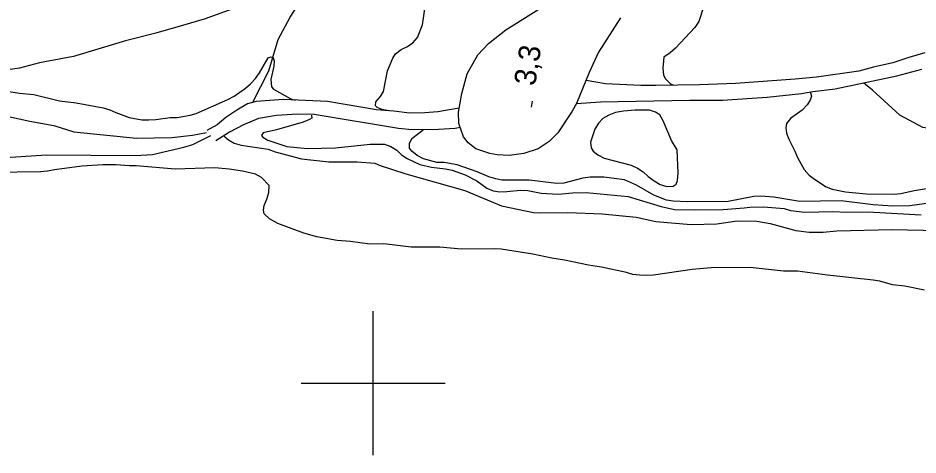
# Model space of a CAD drawing. Extents: x 282461 to 284471, y 5554090 to 5557646.
# Drawn here: x 283150.7 to 283275.7, y 5554590 to 5554650.7 of the extents above; entities that cross this region are included whole.
import ezdxf

# ---------------------------------------------------------------- set-up
doc = ezdxf.new("R2010")
doc.units = 0
for name, color, linetype in [('Niveau 19', 7, 'Continuous'), ('Niveau 2', 7, 'Continuous'), ('Niveau 21', 7, 'Continuous'), ('Niveau 22', 7, 'Continuous'), ('Niveau 3', 7, 'Continuous'), ('Niveau 4', 7, 'Continuous'), ('Niveau 61', 7, 'Continuous')]:
    doc.layers.add(name, color=color, linetype=linetype)

msp = doc.modelspace()

# ---------------------------------------------------------------- linework, layer by layer
at = {"layer": 'Niveau 19'}
for points in [[(283276.62, 5554645.88), (283274.39, 5554645.24), (283272.2, 5554644.48), (283269.52, 5554643.91), (283267.45, 5554643.35), (283261.6, 5554642.52), (283258.63, 5554642.23), (283250.32, 5554641.63), (283245.34, 5554641.44), (283239.25, 5554641.34), (283237.17, 5554641.33), (283232.28, 5554641.59), (283229.59, 5554642.06)], [(283228.24, 5554638.85), (283231.59, 5554639.06), (283243.92, 5554639.3), (283248.51, 5554639.3), (283254.73, 5554639.75), (283259.48, 5554640.23), (283261.06, 5554640.5), (283264.17, 5554640.87), (283272.76, 5554642.67), (283276.22, 5554643.61)], [(283211.95, 5554638.22), (283208.99, 5554637.71), (283207.19, 5554637.55), (283205.05, 5554637.5), (283202.9, 5554637.8), (283200.46, 5554637.99), (283193.65, 5554639.13), (283187.55, 5554639.39), (283183.78, 5554639.14), (283182.56, 5554638.82), (283181.06, 5554637.92), (283179.57, 5554636.89), (283178.36, 5554635.87), (283176.92, 5554635.08)], [(283212.09, 5554635.52), (283211.4, 5554635.38), (283209.08, 5554635.22), (283205.43, 5554635.18), (283203.52, 5554635.37), (283191.82, 5554637.31), (283189.55, 5554637.38), (283186.59, 5554637.2), (283184.1, 5554636.75), (283182.02, 5554635.89), (283180.06, 5554634.86), (283178.16, 5554633.64)]]:
    msp.add_lwpolyline(points, dxfattribs=at)
at = {"layer": 'Niveau 2'}
for points in [[(283202.19, 5554637.81), (283201.27, 5554638.03), (283200.57, 5554638.31), (283200.33, 5554638.54), (283200.38, 5554639.06), (283201.01, 5554639.82), (283201.46, 5554640.53), (283201.99, 5554643.38), (283202.72, 5554645.13), (283203.12, 5554645.77), (283203.92, 5554646.36), (283204.78, 5554646.78), (283205.53, 5554647.26), (283206.15, 5554648.02), (283206.88, 5554649.77), (283207.3, 5554652.62)], [(283245.85, 5554652.09), (283245.24, 5554650.23), (283244.68, 5554649.41), (283242, 5554646.53), (283241.25, 5554645.88), (283240.39, 5554645.29), (283240.24, 5554643.78), (283240.32, 5554642.79), (283240.61, 5554642.28), (283241.32, 5554641.59), (283241.76, 5554641.38)], [(283148.18, 5554640.7), (283150.91, 5554640.28), (283152.89, 5554640.08), (283156.44, 5554639.21), (283158.77, 5554638.95), (283162.49, 5554638.26), (283163.43, 5554637.98), (283164.25, 5554637.59), (283166.11, 5554636.92), (283167.86, 5554636.6), (283168.85, 5554636.56), (283169.83, 5554636.63), (283171.8, 5554636.89), (283172.79, 5554636.91), (283174.58, 5554637.23), (283175.45, 5554637.47), (283179.83, 5554639.4), (283180.69, 5554639.87), (283182.3, 5554641), (283182.99, 5554641.59), (283183.67, 5554642.3), (283184.24, 5554643.12), (283185.42, 5554645.17), (283185.83, 5554645.35), (283186.12, 5554645.18), (283186.24, 5554644.78), (283186.2, 5554644.02), (283185.82, 5554642.16), (283185.9, 5554641.18), (283186.19, 5554640.83), (283188.59, 5554639.48), (283189.16, 5554639.3)], [(283260.76, 5554640.39), (283260.89, 5554639.87), (283260.72, 5554639.29), (283260.27, 5554638.64), (283259.58, 5554637.94), (283257.98, 5554636.75), (283257.41, 5554636.05), (283257.3, 5554635.47), (283257.43, 5554634.72), (283257.73, 5554633.91), (283258.57, 5554632.24), (283258.94, 5554631.32), (283259.89, 5554629.66), (283260.54, 5554628.91), (283261.3, 5554628.35), (283262.94, 5554627.27), (283263.76, 5554626.94), (283265.62, 5554626.56), (283266.55, 5554626.46), (283268.52, 5554626.31), (283272.35, 5554626.26), (283273.28, 5554626.33), (283275.13, 5554626.77), (283276.92, 5554627.03)], [(283242.22, 5554632.39), (283241.45, 5554633.71), (283240.3, 5554636.42), (283239.82, 5554637.28), (283239.24, 5554637.62), (283238.37, 5554637.9), (283236.39, 5554637.92), (283234.77, 5554637.78), (283233.68, 5554637.59), (283232.75, 5554637.23), (283231.89, 5554636.75), (283231.32, 5554636.11), (283230.81, 5554635.29), (283230.2, 5554633.48), (283230.28, 5554632.67), (283230.57, 5554632.21), (283231.22, 5554631.7), (283232.1, 5554631.25), (283235.82, 5554630.27), (283236.7, 5554629.87), (283237.52, 5554629.37), (283238.22, 5554628.68), (283239.04, 5554628.11), (283239.86, 5554627.61), (283240.8, 5554627.33), (283241.66, 5554627.34), (283242.07, 5554627.64), (283242.29, 5554628.17), (283242.39, 5554629.15), (283242.22, 5554632.39)], [(283147.84, 5554637.35), (283152.33, 5554636.37), (283155.65, 5554635.79), (283158.45, 5554634.9), (283167.12, 5554634.05), (283172.06, 5554634.13), (283174.9, 5554634.46), (283176.85, 5554634.81)], [(283191.44, 5554637.22), (283191.48, 5554636.79), (283191.19, 5554636.62), (283190.27, 5554636.25), (283186.57, 5554635.21), (283184.72, 5554634.77), (283184.49, 5554634.42), (283184.67, 5554634.19)], [(283279.21, 5554625.27), (283274.52, 5554624.62), (283272.15, 5554624.58), (283269.47, 5554624.77), (283265, 5554625.34), (283259.25, 5554625.25), (283255.65, 5554625.83), (283253.85, 5554625.98), (283252.86, 5554625.91), (283249.33, 5554625.21), (283243.65, 5554625.18), (283241.67, 5554625.27), (283240.74, 5554625.43), (283238.99, 5554626.1), (283236.59, 5554627.51), (283234.9, 5554628.23), (283232.05, 5554628.6), (283230.13, 5554628.62), (283229.15, 5554628.49), (283226.49, 5554627.76), (283225.51, 5554627.74), (283221.67, 5554628.2), (283217.9, 5554628.2), (283217.03, 5554628.36), (283216.09, 5554628.64), (283214.46, 5554629.37), (283211.66, 5554630.31), (283209.86, 5554630.63), (283208.87, 5554630.67), (283207, 5554631.16), (283206.13, 5554631.61), (283205.36, 5554632.24), (283205.07, 5554632.64), (283205.06, 5554633.28), (283205.39, 5554633.98), (283206.97, 5554635.18)], [(283179.3, 5554634.32), (283179.9, 5554633.79), (283180.72, 5554633.34), (283181.66, 5554633.06), (283185.44, 5554632.48), (283186.38, 5554632.15), (283190.05, 5554631.16), (283193.84, 5554630.75), (283197.79, 5554630.76), (283200.23, 5554630.56), (283200.99, 5554630.23), (283204.55, 5554629.06), (283212.72, 5554626.75), (283217.81, 5554624.62), (283222.3, 5554623.71), (283223.29, 5554623.66), (283227.06, 5554623.72), (283231.83, 5554623.51), (283236.54, 5554623.06), (283239.29, 5554622.46), (283244.17, 5554622.01), (283247.72, 5554622.13), (283250.56, 5554622.52), (283253.29, 5554622.51), (283255.15, 5554622.19), (283258.71, 5554621.2), (283260.58, 5554620.99), (283262.5, 5554620.96), (283264.41, 5554621.17), (283272.02, 5554621.35), (283278.59, 5554621.22)], [(283184.67, 5554634.19), (283185.38, 5554633.74), (283188, 5554632.85), (283190.91, 5554632.61), (283194.8, 5554632.67), (283199.61, 5554633.21), (283201.58, 5554633.18), (283202.46, 5554632.85), (283203.28, 5554632.34), (283203.93, 5554631.71), (283204.75, 5554631.2), (283206.5, 5554630.36), (283208.13, 5554629.98), (283210.05, 5554629.77), (283210.98, 5554629.56), (283212.79, 5554628.95), (283214.43, 5554628.1), (283215.78, 5554627.08), (283216.66, 5554626.69), (283217.59, 5554626.58), (283218.58, 5554626.6), (283220.49, 5554626.8), (283221.48, 5554626.76), (283223.34, 5554626.38), (283225.72, 5554626.25), (283227.69, 5554626.45), (283229.61, 5554626.48), (283235.42, 5554625.93), (283240.03, 5554624.55), (283241.84, 5554624.12), (283244.69, 5554624.05), (283248.63, 5554624.11), (283251.53, 5554624.33), (283252.34, 5554624.46), (283254.2, 5554624.49), (283257.11, 5554624.24), (283257.98, 5554623.96), (283259.96, 5554623.76), (283263.85, 5554623.82), (283265.77, 5554623.74), (283268.73, 5554623.78), (283276.11, 5554623.38)]]:
    msp.add_lwpolyline(points, dxfattribs=at)
at = {"layer": 'Niveau 21'}
msp.add_lwpolyline([(283234.34, 5554650.74), (283231.31, 5554645.98), (283230.02, 5554643.15), (283228.24, 5554638.85), (283227.67, 5554637.78), (283225.66, 5554634.76), (283224.43, 5554633.58), (283222.91, 5554632.54), (283220.95, 5554631.88), (283218.9, 5554631.61), (283217.21, 5554631.7), (283216.22, 5554631.89), (283214.27, 5554632.55), (283213.21, 5554633.4), (283212.56, 5554634.2), (283211.9, 5554636.07), (283211.84, 5554637.63), (283212.32, 5554640.25), (283213.06, 5554642.99), (283214.53, 5554645.61), (283216.01, 5554647.19), (283218.45, 5554649.09), (283225.39, 5554653.49)], dxfattribs=at)
at = {"layer": 'Niveau 22'}
for points in [[(283183.28, 5554639.01), (283185.51, 5554643.37), (283186.83, 5554647.74), (283188.47, 5554650.84), (283191.7, 5554655.9), (283194.32, 5554658.84), (283199.12, 5554663.61), (283201.4, 5554666.26), (283203.17, 5554668.15), (283204.71, 5554669.51), (283207.19, 5554670.94), (283218.89, 5554675.85)], [(283189.97, 5554656.34), (283187.82, 5554654.98), (283184.48, 5554653.47), (283176.52, 5554650.57), (283173.52, 5554649.67), (283169.83, 5554648.62), (283165.61, 5554647.57), (283158.39, 5554645.37), (283153.65, 5554644.5), (283150.88, 5554643.76), (283147.93, 5554643.36), (283143.4, 5554643.04), (283140.95, 5554642.24)], [(283291.45, 5554620.48), (283291.23, 5554622.56), (283289.87, 5554627.4), (283288.81, 5554630.8), (283287.03, 5554633.91), (283286.21, 5554634.65), (283285.57, 5554634.99), (283283.61, 5554635.28), (283281.24, 5554635.07), (283279.44, 5554635.04), (283276.36, 5554635.51), (283273.14, 5554637.21), (283269.36, 5554640.71), (283268.17, 5554641.68)], [(283147.47, 5554631.23), (283154.66, 5554631.73), (283166.97, 5554631.62), (283169.35, 5554631.78), (283173.7, 5554632.79), (283174.97, 5554633.15), (283177.45, 5554634.38)]]:
    msp.add_lwpolyline(points, dxfattribs=at)
at = {"layer": 'Niveau 3'}
msp.add_line((283222.02, 5554638.36), (283222.14, 5554639.15), dxfattribs=at)
at = {"layer": 'Niveau 4'}
msp.add_lwpolyline([(283276.56, 5554612.91), (283273.87, 5554613.45), (283272.12, 5554613.66), (283270.37, 5554614.15), (283269.44, 5554614.31), (283263.09, 5554614.97), (283258.95, 5554615.54), (283256.98, 5554615.57), (283252.37, 5554616.08), (283246.97, 5554616), (283244.3, 5554615.78), (283238.96, 5554615), (283237.97, 5554614.93), (283236.99, 5554614.97), (283236.05, 5554615.07), (283235.18, 5554615.35), (283231.73, 5554616.11), (283229.93, 5554616.37), (283226.6, 5554617.07), (283224.8, 5554617.34), (283222.17, 5554617.93), (283217.8, 5554618.62), (283216.93, 5554618.67), (283212.22, 5554618.59), (283209.25, 5554618.89), (283205.3, 5554618.89), (283201.51, 5554619.35), (283199.54, 5554619.32), (283196.86, 5554619.69), (283195, 5554619.83), (283192.2, 5554620.31), (283190.39, 5554620.81), (283186.76, 5554622.15), (283185.59, 5554622.82), (283184.88, 5554623.51), (283184.76, 5554624.03), (283184.86, 5554624.67), (283185.26, 5554625.55), (283185.53, 5554626.48), (283185.57, 5554627.47), (283184.51, 5554628.56), (283183.69, 5554629.01), (283181.88, 5554629.45), (283180.02, 5554629.71), (283178.04, 5554629.91), (283172.52, 5554629.71), (283167.11, 5554630.2), (283166.18, 5554630.19), (283164.26, 5554630.33), (283162.46, 5554630.31), (283159.55, 5554630.14), (283155.73, 5554629.62), (283154.8, 5554629.43), (283153.81, 5554629.36), (283140.74, 5554629.15)], dxfattribs=at)
at = {"layer": 'Niveau 61'}
for points in [[(283200, 5554590), (283200, 5554610)], [(283190, 5554600), (283210, 5554600)]]:
    msp.add_lwpolyline(points, dxfattribs=at)

# ---------------------------------------------------------------- texts
at = {"layer": 'Niveau 3'}
msp.add_text('3,3  ', height=3, rotation=81.0957, dxfattribs=at).set_placement((283222.5, 5554641.2))

doc.saveas('drawing.dxf')
